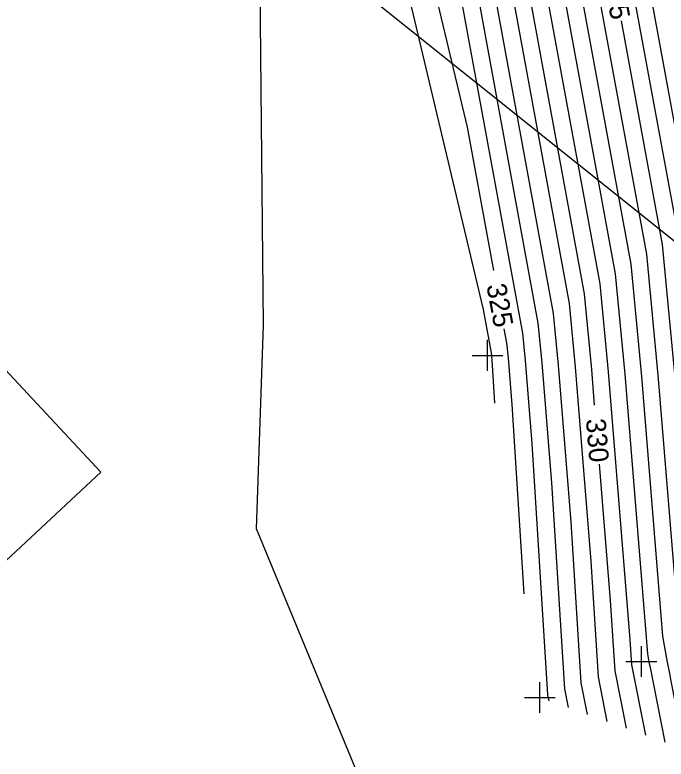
# Model space of a CAD drawing. Extents: x 487096 to 489566, y 221939 to 224454.
# Drawn here: x 488250.6 to 488356.5, y 222860.8 to 222981.8 of the extents above; entities that cross this region are included whole.
import ezdxf

# ---------------------------------------------------------------- set-up
doc = ezdxf.new("R2010")
doc.units = 0
for name, color, linetype in [('SV_CTRL_BM_INFO_BOX', 7, 'Continuous'), ('SV_CTRL_TIE_BOX', 7, 'Continuous'), ('SV_SURF_INDEX_CONTOUR', 7, 'Continuous'), ('SV_SURF_INTER_CONTOUR', 7, 'Continuous'), ('SV_SURF_SPOT', 7, 'Continuous'), ('SV_WATR_INWETF', 7, 'Continuous')]:
    doc.layers.add(name, color=color, linetype=linetype)

msp = doc.modelspace()

# ---------------------------------------------------------------- linework, layer by layer
at = {"layer": 'SV_CTRL_BM_INFO_BOX'}
msp.add_line((488260.98, 223022.49), (488394.91, 222915.38), dxfattribs=at)
at = {"layer": 'SV_CTRL_TIE_BOX'}
msp.add_lwpolyline([(488124.26, 222940.67), (488206.1, 222852.91), (488264.61, 222907.47), (488182.77, 222995.23)], close=True, dxfattribs=at)
at = {"layer": 'SV_SURF_INDEX_CONTOUR'}
for points in [[(488328.45, 222940.22), (488324.17, 222963.52), (488311, 223019), (488310.08, 223024.61)], [(488344.86, 222918.34), (488344.39, 222924.14), (488343.22, 222936.46), (488330.92, 223003.53)], [(488349.18, 222980.78), (488355.84, 222944.47), (488357.94, 222922.29), (488360.16, 222895.18)], [(488333.38, 222887.71), (488331.46, 222918.48), (488330.84, 222925.99), (488330.61, 222928.46), (488330.18, 222930.78)], [(488350.02, 222865.85), (488348.18, 222875.17), (488347.46, 222886.64), (488345.65, 222908.77)]]:
    msp.add_lwpolyline(points, dxfattribs=at)
at = {"layer": 'SV_SURF_INTER_CONTOUR'}
for points in [[(488308.1, 223280.91), (488302.87, 223215.26), (488303.09, 223212.1), (488314.33, 223179.75), (488315.49, 223170.68), (488321.71, 223124.75), (488322.05, 223123.29), (488321.83, 223122.48), (488321.6, 223062.82), (488322.18, 223058.03), (488327.26, 223019.75), (488327.22, 223011.73), (488327.32, 223007.77), (488340.7, 222934.86), (488341.68, 222924.51), (488344.26, 222893.01), (488345.44, 222874.2), (488346.87, 222866.97)], [(488362.65, 222861.37), (488360.69, 222871.28), (488360.25, 222873.42), (488359.64, 222876.54), (488358.42, 222883.72), (488355.23, 222922.66), (488353.32, 222942.87), (488343.6, 222995.81), (488343.29, 223008.32), (488343.42, 223033.62), (488341.25, 223049.9), (488337.65, 223079.89), (488337.73, 223100.91), (488343.22, 223121.57), (488334.61, 223158.85), (488333.23, 223169.06), (488330.1, 223193.59), (488324.97, 223208.36), (488320.92, 223265.03)], [(488359.49, 222862.49), (488357.31, 222873.5), (488357.06, 222874.76), (488356.7, 222876.6), (488355.97, 222880.83), (488352.52, 222923.03), (488350.79, 222941.27), (488340.35, 222998.2), (488340.07, 223009), (488340.19, 223030.85), (488337.44, 223051.53), (488334.44, 223076.48), (488334.55, 223105.23), (488338.98, 223121.91), (488332.03, 223152.03), (488329.68, 223169.38), (488326.95, 223190.82), (488320.59, 223209.11), (488317.31, 223255.08)], [(488330.36, 223253.85), (488333.72, 223206.86), (488336.41, 223199.13), (488339.34, 223176.14), (488341.3, 223168.89), (488341.3, 223168.78), (488341.3, 223168.7), (488341.25, 223167.91), (488342.11, 223162.38), (488351.69, 223120.88), (488344.09, 223092.29), (488344.07, 223086.72), (488348.88, 223046.65), (488349.88, 223039.17), (488349.71, 223006.96), (488350.12, 222991.02), (488358.36, 222946.07), (488360.64, 222921.92), (488363.3, 222889.49), (488365.53, 222876.42), (488366.64, 222870.73), (488367.44, 222866.83), (488368.96, 222859.13)], [(488356.34, 222863.61), (488353.94, 222875.72), (488353.86, 222876.1), (488353.75, 222876.66), (488353.53, 222877.95), (488349.81, 222923.4), (488348.27, 222939.67), (488337.09, 223000.59), (488336.86, 223009.68), (488336.96, 223028.07), (488333.62, 223053.15), (488331.23, 223073.06), (488331.37, 223109.54), (488334.75, 223122.26), (488329.45, 223145.21), (488326.14, 223169.71), (488323.79, 223188.06), (488316.22, 223209.85), (488313.7, 223245.12)], [(488353.18, 222864.73), (488350.92, 222876.14), (488350.66, 222880.27), (488347.1, 222923.77), (488345.75, 222938.07), (488333.84, 223002.98), (488333.65, 223010.37), (488333.72, 223025.3), (488329.81, 223054.78), (488328.02, 223069.65), (488328.19, 223113.86), (488330.51, 223122.6), (488326.87, 223138.39), (488322.59, 223170.03), (488320.64, 223185.29), (488311.84, 223210.6), (488310.09, 223235.17)], [(488372.12, 222858.01), (488370.81, 222864.61), (488369.84, 222869.39), (488368.47, 222876.36), (488365.75, 222892.37), (488363.35, 222921.55), (488360.89, 222947.67), (488353.37, 222988.63), (488352.92, 223006.27), (488353.11, 223041.95), (488352.7, 223045.03), (488348.94, 223076.26), (488347.53, 223089.21), (488348.29, 223091.81), (488355.92, 223120.53), (488348.77, 223151.52), (488346.42, 223166.72), (488346.54, 223168.9), (488346.55, 223169.1), (488346.56, 223169.4), (488341.16, 223189.35), (488339.56, 223201.89), (488338.09, 223206.12), (488336.26, 223231.76)], [(488343.71, 222868.09), (488342.69, 222873.22), (488341.06, 222899.38), (488338.97, 222924.88), (488338.18, 222933.26), (488324.07, 223010.16), (488324.01, 223012.41), (488324.03, 223016.97), (488318.59, 223057.97), (488318.37, 223059.28), (488318.28, 223110.78), (488316.49, 223137.44), (488311.94, 223171.01), (488311.18, 223176.99), (488302.67, 223201.46)], [(488303.92, 223186.04), (488308.03, 223174.22), (488308.39, 223171.33), (488310.59, 223155.12), (488314.64, 223094.97), (488314.71, 223053.17), (488319.49, 223024.11), (488320.8, 223014.2), (488320.8, 223013.1), (488320.81, 223012.55), (488335.65, 222931.66), (488336.26, 222925.25), (488337.86, 222905.75), (488339.95, 222872.25), (488340.55, 222869.21)], [(488304.96, 223168.81), (488311, 223079.17), (488311.05, 223047.06), (488316.22, 223015.62), (488321.56, 222993.14), (488333.13, 222930.06), (488333.55, 222925.62), (488334.66, 222912.11), (488337.21, 222871.28), (488337.4, 222870.33)], [(488328.64, 222918.67), (488328.26, 222924.85), (488328.13, 222926.36), (488328.08, 222926.86), (488326.79, 222933.91), (488305.79, 223022.38), (488303.74, 223034.84), (488303.72, 223047.56), (488301.33, 223083.09)]]:
    msp.add_lwpolyline(points, dxfattribs=at)
at = {"layer": 'SV_SURF_SPOT'}
for p, q in [((488327.45, 222923.95), (488327.45, 222928.96)), ((488324.95, 222926.45), (488329.95, 222926.45)), ((488327.45, 222926.45), (488327.45, 222926.45)), ((488352.46, 222874.19), (488352.46, 222879.19)), ((488349.96, 222876.69), (488354.96, 222876.69)), ((488352.46, 222876.69), (488352.46, 222876.69)), ((488335.96, 222868.34), (488335.96, 222873.34)), ((488333.46, 222870.84), (488338.46, 222870.84)), ((488335.96, 222870.84), (488335.96, 222870.84))]:
    msp.add_line(p, q, dxfattribs=at)
at = {"layer": 'SV_WATR_INWETF'}
msp.add_lwpolyline([(488317.45, 222831.55), (488289.87, 222898.26), (488291.06, 222931.37), (488290.46, 222991.69), (488252.55, 223050.25)], dxfattribs=at)

# ---------------------------------------------------------------- texts
at = {"layer": 'SV_SURF_INDEX_CONTOUR'}
for s, rotation, p in [('335', 280.3979, (488346.26, 222987.82)), ('325', 280.3979, (488327.26, 222937.82)), ('330', 274.6839, (488343.44, 222916.07))]:
    msp.add_text(s, height=3.2, rotation=rotation, dxfattribs=at).set_placement(p)

doc.saveas('drawing.dxf')
